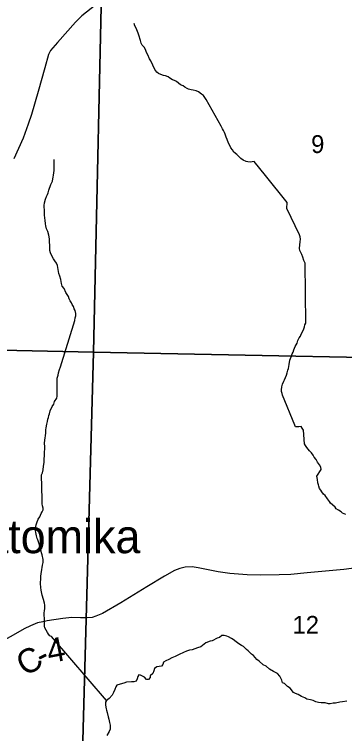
# Model space of a CAD drawing. Extents: x 0 to 34, y 0 to 22.
# Drawn here: x 4.859 to 5.636, y 18.529 to 20.219 of the extents above; entities that cross this region are included whole.
import ezdxf

# ---------------------------------------------------------------- set-up
doc = ezdxf.new("R2010")
doc.units = 0
for name, color, linetype in [('GM_X_Corporation', 7, 'Continuous'), ('GM_X_County_Road', 7, 'Continuous'), ('GM_X_County_Road_Text', 7, 'Continuous'), ('GM_X_Minor_River', 7, 'Continuous'), ('GM_X_Section_Text', 7, 'Continuous'), ('GM_X_Township_Road', 7, 'Continuous'), ('GM_X_Unincorporated_Text', 7, 'Continuous')]:
    doc.layers.add(name, color=color, linetype=linetype)

msp = doc.modelspace()

# ---------------------------------------------------------------- linework, layer by layer
at = {"layer": 'GM_X_Corporation'}
for points in [[(4.0987, 20.3855), (4.6031, 20.3739), (4.6046, 20.4596), (5.0677, 20.4508), (5.0447, 19.4257), (4.5747, 19.4359), (4.5724, 19.3635), (4.0627, 19.3751)], [(6.1008, 20.4274), (6.0762, 19.405), (5.0447, 19.4257), (5.0677, 20.4508)], [(5.0447, 19.4257), (5.0167, 18.3983), (4.5438, 18.4054), (4.5458, 18.4688), (4.5582, 18.8561), (4.2447, 18.8641), (4.0466, 18.8695), (4.0627, 19.3751), (4.5724, 19.3635), (4.5747, 19.4359)], [(5.0447, 19.4257), (6.0762, 19.405), (6.0547, 18.3798), (5.0167, 18.3983)]]:
    msp.add_lwpolyline(points, close=True, dxfattribs=at)
at = {"layer": 'GM_X_County_Road'}
for points in [[(5.6759, 18.9204), (5.6339, 18.9145), (5.5478, 18.9073), (5.5091, 18.9029), (5.4821, 18.9025), (5.4381, 18.9016), (5.4069, 18.9025), (5.3656, 18.905), (5.3387, 18.9091), (5.311, 18.915), (5.2913, 18.919), (5.2768, 18.9213), (5.2611, 18.9202), (5.2485, 18.9175), (5.236, 18.9127), (5.212, 18.8989), (5.1707, 18.8737), (5.1091, 18.8365), (5.066, 18.8114), (5.0508, 18.8048), (5.0418, 18.8023), (5.03, 18.8012), (5.0146, 18.8012), (4.9942, 18.8017), (4.9729, 18.7994), (4.9364, 18.7944), (4.9258, 18.792)], [(4.9258, 18.792), (4.9133, 18.7892), (4.8967, 18.7826), (4.8818, 18.7751), (4.856, 18.7606), (4.8297, 18.7459), (4.8129, 18.7375), (4.8008, 18.7345), (4.7883, 18.7345), (4.7769, 18.7364), (4.7556, 18.7429), (4.712, 18.7577), (4.6735, 18.7721), (4.6495, 18.7802), (4.6359, 18.7847), (4.6208, 18.79)]]:
    msp.add_lwpolyline(points, dxfattribs=at)
at = {"layer": 'GM_X_Minor_River'}
for points in [[(5.5399, 19.6408), (5.5376, 19.6487), (5.535, 19.6548), (5.5327, 19.6597), (5.5308, 19.6646), (5.53, 19.6692), (5.5303, 19.6779), (5.5315, 19.6844), (5.5322, 19.6912), (5.531, 19.6965), (5.5299, 19.7014), (5.4998, 19.7632), (5.5009, 19.7773), (5.4495, 19.8401), (5.4233, 19.8731), (5.4134, 19.8716), (5.4081, 19.8723), (5.404, 19.8735), (5.3971, 19.8768), (5.3918, 19.8806), (5.3869, 19.8852), (5.3819, 19.8901), (5.3755, 19.8954), (5.372, 19.9007), (5.3682, 19.9052), (5.3667, 19.9094), (5.3629, 19.9162), (5.3599, 19.925), (5.3572, 19.9306), (5.3549, 19.9375), (5.353, 19.9413), (5.3507, 19.9462), (5.3488, 19.9504), (5.3454, 19.956), (5.3099, 20.0193), (5.3035, 20.0281), (5.2989, 20.0315), (5.2921, 20.0368), (5.2868, 20.039), (5.2799, 20.0409), (5.2746, 20.042), (5.2689, 20.0435), (5.2651, 20.0451), (5.2602, 20.0477), (5.2557, 20.0511), (5.25, 20.0537), (5.2454, 20.0575), (5.2401, 20.0609), (5.2355, 20.064), (5.2306, 20.0655), (5.2245, 20.0693), (5.2204, 20.0719), (5.2143, 20.0745), (5.2097, 20.0757), (5.2033, 20.0779), (5.1976, 20.0802), (5.1938, 20.0832), (5.1896, 20.0897), (5.185, 20.0995), (5.1801, 20.1098), (5.1767, 20.1143), (5.1732, 20.1238), (5.1694, 20.1295), (5.1671, 20.1363), (5.1641, 20.142), (5.1599, 20.1469), (5.1576, 20.1511), (5.1557, 20.1579), (5.1519, 20.1704), (5.1503, 20.1746), (5.1473, 20.1826), (5.1458, 20.1867), (5.1427, 20.1917), (5.1404, 20.1973)], [(5.0022, 19.5229), (4.9999, 19.5271), (4.998, 19.5324), (4.9946, 19.5373), (4.9934, 19.5415), (4.9904, 19.5456), (4.9877, 19.5506), (4.9866, 19.5563), (4.9801, 19.5653), (4.9763, 19.5748), (4.9713, 19.5805), (4.9702, 19.5866), (4.9683, 19.5961), (4.966, 19.6036), (4.9633, 19.6105), (4.9621, 19.6199), (4.9602, 19.629), (4.9579, 19.6343), (4.9545, 19.6396), (4.9511, 19.6446), (4.9476, 19.6503), (4.9442, 19.6586), (4.9427, 19.6639), (4.9423, 19.673), (4.9422, 19.6787), (4.9419, 19.6825), (4.9415, 19.6916), (4.9399, 19.7003), (4.9376, 19.7087), (4.9349, 19.7155), (4.933, 19.7219), (4.9323, 19.7272), (4.9311, 19.7356), (4.9303, 19.7398), (4.9295, 19.7481), (4.9295, 19.7606), (4.9291, 19.7652), (4.9291, 19.7697), (4.9302, 19.7766), (4.9325, 19.7845), (4.9343, 19.7914), (4.937, 19.7959), (4.9385, 19.7997), (4.94, 19.8058), (4.9445, 19.8195), (4.9486, 19.8274), (4.9498, 19.8324), (4.9505, 19.8369), (4.9512, 19.8411), (4.9527, 19.8525), (4.9527, 19.8733), (4.9523, 19.8779)], [(5.6383, 19.0439), (5.6311, 19.0473), (5.6273, 19.0503), (5.6212, 19.0541), (5.6163, 19.0575), (5.6136, 19.0613), (5.6076, 19.0666), (5.6026, 19.0708), (5.6, 19.0746), (5.5954, 19.081), (5.5897, 19.0889), (5.5859, 19.092), (5.5825, 19.0969), (5.5802, 19.1011), (5.5771, 19.1048), (5.5748, 19.1102), (5.5741, 19.1139), (5.5729, 19.1181), (5.5718, 19.1261), (5.5702, 19.1344), (5.5808, 19.1496), (5.5796, 19.1549), (5.5766, 19.1606), (5.5724, 19.167), (5.5686, 19.1731), (5.564, 19.1784), (5.5621, 19.1833), (5.5576, 19.189), (5.553, 19.1932), (5.5499, 19.1977), (5.5473, 19.2015), (5.5439, 19.2064), (5.5412, 19.2102), (5.5388, 19.2425), (5.5362, 19.2466), (5.5335, 19.2504), (5.5278, 19.25), (5.5202, 19.25), (5.5187, 19.2538), (5.4897, 19.3247), (5.4889, 19.3285), (5.4874, 19.333), (5.487, 19.3372), (5.4881, 19.344), (5.49, 19.3501), (5.4926, 19.3569), (5.4945, 19.3607), (5.4968, 19.3657), (5.4987, 19.371), (5.5005, 19.3767), (5.5024, 19.3831), (5.5035, 19.3873), (5.5043, 19.3918), (5.5054, 19.3964), (5.5073, 19.4063), (5.5084, 19.4108), (5.5106, 19.4157), (5.5121, 19.4214), (5.5144, 19.4252), (5.5163, 19.4306), (5.5197, 19.4389), (5.5238, 19.4469), (5.5261, 19.4526), (5.5291, 19.459), (5.5317, 19.4632), (5.5336, 19.4674), (5.5366, 19.4731), (5.5396, 19.4803), (5.5415, 19.4845), (5.5426, 19.4894), (5.5445, 19.4932), (5.5433, 19.6343), (5.5399, 19.6408)], [(5.0754, 18.6071), (4.9462, 18.757), (4.9424, 18.7593), (4.9393, 18.7631), (4.937, 18.7669), (4.9336, 18.7722), (4.9306, 18.7779), (4.9302, 18.7816), (4.9301, 18.7957), (4.9297, 18.8014), (4.9293, 18.8059), (4.9293, 18.8127), (4.9301, 18.8173), (4.9304, 18.823), (4.9304, 18.8313), (4.9296, 18.8355), (4.9277, 18.8446), (4.9246, 18.8541), (4.9231, 18.8624), (4.9219, 18.8662), (4.9215, 18.8723), (4.9208, 18.8817), (4.9208, 18.8859), (4.9211, 18.8905), (4.9215, 18.8984), (4.9222, 18.9053), (4.923, 18.9091), (4.9252, 18.925), (4.9263, 18.9314), (4.9263, 18.9383), (4.9243, 18.9493), (4.9228, 18.9542), (4.9213, 18.9614), (4.9194, 18.9656), (4.9178, 18.9731), (4.9167, 18.9777), (4.914, 18.9841), (4.9129, 18.9879), (4.9113, 18.9936), (4.9098, 19.0019), (4.909, 19.0065), (4.9094, 19.011), (4.9097, 19.0156), (4.9105, 19.0194), (4.912, 19.0243), (4.9146, 19.0327), (4.9188, 19.0384), (4.9218, 19.0463), (4.9244, 19.0501), (4.9263, 19.0547), (4.9263, 19.0585), (4.9255, 19.0646), (4.9247, 19.0691), (4.9243, 19.0748), (4.9243, 19.079), (4.9226, 19.137), (4.9253, 19.1419), (4.9264, 19.1491), (4.9275, 19.1579), (4.929, 19.1662), (4.929, 19.1715), (4.9293, 19.1753), (4.9297, 19.1814), (4.9301, 19.1912), (4.9304, 19.1977), (4.9304, 19.2041), (4.93, 19.2106), (4.9307, 19.2193), (4.9311, 19.2231), (4.9322, 19.2292), (4.933, 19.2349), (4.9333, 19.239), (4.9333, 19.2428), (4.9341, 19.2478), (4.9352, 19.2561), (4.937, 19.2626), (4.9378, 19.2679), (4.9393, 19.272), (4.94, 19.2762), (4.9415, 19.2804), (4.943, 19.2876), (4.9479, 19.2975), (4.9517, 19.3032), (4.9536, 19.3092), (4.9585, 19.3176), (4.96, 19.3222), (4.96, 19.3282), (4.9596, 19.3354), (4.9599, 19.3453), (4.9595, 19.3521), (4.9595, 19.3593), (4.9599, 19.3639), (4.9617, 19.3711), (4.9628, 19.3772), (4.9651, 19.3848), (4.9674, 19.3912), (5.0008, 19.4998), (5.0022, 19.5058), (5.0034, 19.5108), (5.0037, 19.5161), (5.0022, 19.5229)], [(5.6412, 18.6052), (5.631, 18.6036), (5.6249, 18.6029), (5.6147, 18.601), (5.6086, 18.6006), (5.6022, 18.5994), (5.598, 18.5994), (5.5904, 18.6013), (5.5806, 18.6017), (5.5745, 18.6024), (5.5677, 18.6035), (5.5616, 18.6069), (5.5559, 18.6088), (5.5472, 18.6099), (5.5419, 18.613), (5.5343, 18.6163), (5.5267, 18.6209), (5.5199, 18.6235), (5.5153, 18.6258), (5.5077, 18.636), (5.5016, 18.6398), (5.494, 18.6466), (5.4899, 18.6485), (5.4879, 18.6549), (5.4834, 18.664), (5.478, 18.6701), (5.4682, 18.6754), (5.4591, 18.6803), (5.4515, 18.6878), (5.4443, 18.6909), (5.4348, 18.6996), (5.4291, 18.7033), (5.4211, 18.7124), (5.4165, 18.7158), (5.4093, 18.7238), (5.4051, 18.7268), (5.3979, 18.7336), (5.3933, 18.7359), (5.3873, 18.74), (5.3808, 18.7446), (5.3736, 18.7506), (5.3698, 18.7529), (5.363, 18.7567), (5.3584, 18.7578), (5.3523, 18.7597), (5.347, 18.7597), (5.3414, 18.7551), (5.3357, 18.7532), (5.324, 18.7471)], [(5.324, 18.7471), (5.3194, 18.7464), (5.3096, 18.7422), (5.2975, 18.7334), (5.2899, 18.7311), (5.2774, 18.7262), (5.271, 18.725), (5.2642, 18.7231), (5.2566, 18.7201), (5.2464, 18.7148), (5.2373, 18.7102), (5.2297, 18.7071), (5.2225, 18.7033), (5.215, 18.6999), (5.2101, 18.6969), (5.2078, 18.6912), (5.2048, 18.6874), (5.1938, 18.6858), (5.1889, 18.6824), (5.187, 18.6767), (5.1844, 18.6706), (5.1787, 18.665), (5.178, 18.6608), (5.1746, 18.6562), (5.17, 18.6562), (5.1651, 18.6615), (5.156, 18.6668), (5.1518, 18.6676), (5.1492, 18.6634), (5.148, 18.6577), (5.1458, 18.6524), (5.1397, 18.6505), (5.1348, 18.6505), (5.1231, 18.6501), (5.1166, 18.6481), (5.1079, 18.6455), (5.0996, 18.6428), (5.0977, 18.639), (5.0951, 18.6329), (5.0921, 18.6257), (5.0887, 18.6193), (5.0823, 18.6117), (5.0754, 18.6071), (5.0736, 18.6029), (5.0732, 18.5957), (5.0747, 18.5878), (5.0759, 18.584), (5.0774, 18.5787), (5.0797, 18.5684), (5.0809, 18.5635), (5.0828, 18.5552), (5.0843, 18.5491), (5.084, 18.5396), (5.0817, 18.5343), (5.0768, 18.5245)]]:
    msp.add_lwpolyline(points, dxfattribs=at)
at = {"layer": 'GM_X_Township_Road'}
msp.add_lwpolyline([(5.0509, 20.2412), (5.0176, 20.2153), (5.003, 20.201), (4.9607, 20.1531), (4.9437, 20.1344), (4.9391, 20.1249), (4.9308, 20.0935), (4.915, 20.038), (4.8989, 19.9834), (4.8915, 19.9609), (4.8795, 19.9279), (4.8575, 19.8795)], dxfattribs=at)

# ---------------------------------------------------------------- texts
at = {"layer": 'GM_X_County_Road_Text'}
for s, rotation, p in [('4', 11.1446, (4.941, 18.6939)), ('C', 29.2453, (4.8837, 18.6625)), ('-', 25.9751, (4.9237, 18.6849))]:
    msp.add_text(s, height=0.0568, rotation=rotation, dxfattribs=at).set_placement(p)
at = {"layer": 'GM_X_Section_Text'}
for s, height, p in [('9', 0.0419, (5.557, 19.8932)), ('12', 0.04186, (5.5133, 18.7639))]:
    msp.add_text(s, height=height, rotation=0, dxfattribs=at).set_placement(p)
at = {"layer": 'GM_X_Unincorporated_Text'}
msp.add_text('Wakatomika', height=0.07898, rotation=0, dxfattribs=at).set_placement((4.5745, 18.9531))

doc.saveas('drawing.dxf')
